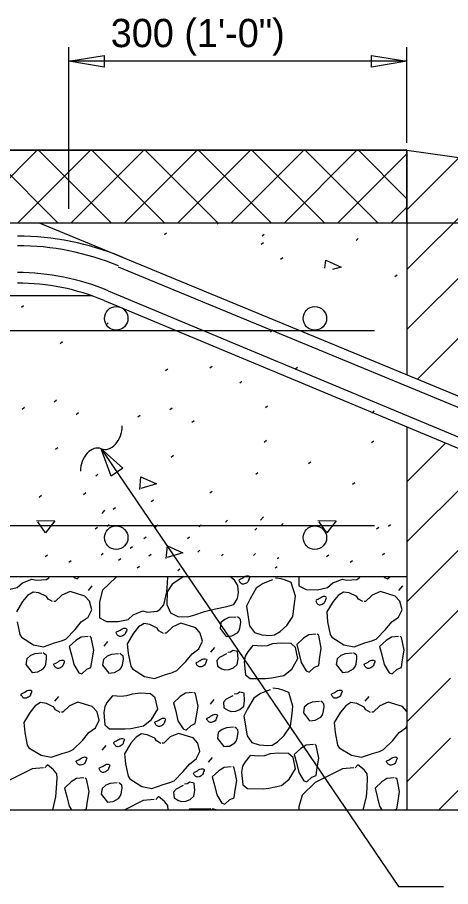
# Model space of a CAD drawing. Extents: x 3239 to 4230, y -4276 to -2494.
# Drawn here: x 3504.5 to 3550.5, y -4204.4 to -4112.2 of the extents above; entities that cross this region are included whole.
import ezdxf

# ---------------------------------------------------------------- set-up
doc = ezdxf.new("R2010")
doc.units = 0
doc.layers.add('2', color=7, linetype='Continuous')

msp = doc.modelspace()

# ---------------------------------------------------------------- linework, layer by layer
at = {"layer": '2'}
for p, q in [((3510.009, -4132.49), (3510.009, -4115.341)), ((3545.886, -4125.509), (3545.886, -4115.341)), ((3545.886, -4116.841), (3510.009, -4116.841)), ((3367.086, -4126.29), (3545.886, -4126.29)), ((3498.953, -4133.99), (3506.653, -4126.29)), ((3501.149, -4126.29), (3508.849, -4133.99)), ((3504.61, -4133.99), (3512.31, -4126.29)), ((3506.806, -4126.29), (3514.506, -4133.99)), ((3510.267, -4133.99), (3517.967, -4126.29)), ((3512.463, -4126.29), (3520.163, -4133.99)), ((3515.924, -4133.99), (3523.624, -4126.29)), ((3518.12, -4126.29), (3525.82, -4133.99)), ((3521.581, -4133.99), (3529.281, -4126.29)), ((3523.777, -4126.29), (3531.477, -4133.99)), ((3527.237, -4133.99), (3534.937, -4126.29)), ((3529.434, -4126.29), (3537.134, -4133.99)), ((3532.894, -4133.99), (3540.594, -4126.29)), ((3535.091, -4126.29), (3542.791, -4133.99)), ((3538.551, -4133.99), (3545.886, -4126.656)), ((3540.747, -4126.29), (3545.886, -4131.428)), ((3545.886, -4126.29), (3545.886, -4150.107)), ((3545.886, -4126.29), (3601.998, -4133.99)), ((3545.886, -4132.595), (3551.43, -4127.051)), ((3545.886, -4138.955), (3557.022, -4127.818)), ((3545.952, -4145.253), (3562.618, -4128.586)), ((3547, -4150.568), (3568.214, -4129.354)), ((3544.208, -4133.99), (3545.886, -4132.313)), ((3363.086, -4133.99), (3601.998, -4133.99)), ((3506.854, -4133.99), (3609.598, -4176.416)), ((3525.77, -4134.077), (3525.879, -4133.99)), ((3520.155, -4135.219), (3520.388, -4135.033)), ((3530.522, -4135.382), (3530.755, -4135.196)), ((3540.491, -4135.846), (3540.724, -4135.659)), ((3530.429, -4136.267), (3530.662, -4136.081)), ((3532.477, -4137.849), (3532.71, -4137.663)), ((3515.238, -4138.666), (3628.011, -4185.234)), ((3544.615, -4139.69), (3544.848, -4139.503)), ((3514.182, -4141.195), (3625.358, -4187.612)), ((3351.09, -4141.69), (3512.455, -4141.69)), ((3513.749, -4142.231), (3609.598, -4182.249)), ((3504.974, -4142.936), (3505.207, -4142.75)), ((3513.967, -4144.8), (3514.2, -4144.614)), ((3311.806, -4145.411), (3542.451, -4145.411)), ((3531.417, -4145.541), (3531.65, -4145.355)), ((3509.097, -4146.78), (3509.33, -4146.594)), ((3520.28, -4149.669), (3520.513, -4149.483)), ((3524.984, -4149.387), (3525.217, -4149.201)), ((3534.05, -4149.479), (3534.283, -4149.292)), ((3528.152, -4150.971), (3528.385, -4150.785)), ((3505.057, -4153.751), (3505.29, -4153.564)), ((3508.468, -4152.977), (3508.701, -4152.791)), ((3530.878, -4153.604), (3531.111, -4153.418)), ((3510.794, -4154.314), (3511.027, -4154.128)), ((3517.333, -4154.587), (3517.566, -4154.401)), ((3520.744, -4153.814), (3520.977, -4153.627)), ((3542.178, -4154.141), (3542.411, -4153.955)), ((3523.07, -4155.151), (3523.303, -4154.964)), ((3545.886, -4155.648), (3545.886, -4164.49)), ((3530.751, -4157.251), (3530.984, -4157.064)), ((3542.132, -4157.31), (3542.365, -4157.123)), ((3508.608, -4158.01), (3508.841, -4157.823)), ((3545.886, -4161.485), (3550.003, -4157.367)), ((3520.883, -4158.846), (3521.116, -4158.66)), ((3535.457, -4159.534), (3535.69, -4159.348)), ((3545.886, -4167.849), (3554.493, -4159.242)), ((3512.869, -4160.85), (3513.102, -4160.663)), ((3529.842, -4160.676), (3530.075, -4160.489)), ((3540.117, -4161.724), (3540.35, -4161.538)), ((3545.886, -4174.213), (3558.982, -4161.116)), ((3511.564, -4162.807), (3511.797, -4162.62)), ((3524.973, -4162.656), (3525.206, -4162.469)), ((3506.861, -4163.089), (3507.094, -4162.903)), ((3518.763, -4163.576), (3518.996, -4163.389)), ((3545.886, -4180.577), (3563.472, -4162.99)), ((3514.733, -4164.391), (3514.966, -4164.205)), ((3545.886, -4164.49), (3545.886, -4196.29)), ((3526.634, -4165.75), (3526.867, -4165.563)), ((3310.367, -4166.121), (3542.451, -4166.121)), ((3512.816, -4166.476), (3513.049, -4166.29)), ((3514.075, -4166.196), (3514.308, -4166.01)), ((3519.213, -4166.243), (3519.446, -4166.056)), ((3523.833, -4166.243), (3524.066, -4166.056)), ((3529.74, -4166.594), (3529.973, -4166.407)), ((3532.541, -4166.101), (3532.774, -4165.914)), ((3542.675, -4166.476), (3542.908, -4166.29)), ((3543.933, -4166.196), (3544.166, -4166.01)), ((3517.979, -4167.505), (3518.212, -4167.318)), ((3522.599, -4167.505), (3522.832, -4167.318)), ((3516.523, -4168.524), (3516.756, -4168.338)), ((3507.511, -4169.415), (3507.744, -4169.229)), ((3513.426, -4169.226), (3513.659, -4169.04)), ((3518.512, -4169.344), (3518.745, -4169.157)), ((3523.694, -4168.934), (3523.927, -4168.747)), ((3526.231, -4169.28), (3526.404, -4169.142)), ((3529.6, -4169.285), (3529.833, -4169.098)), ((3537.37, -4169.415), (3537.603, -4169.229)), ((3543.285, -4169.226), (3543.518, -4169.04)), ((3510.015, -4170), (3510.248, -4169.813)), ((3515.288, -4169.787), (3515.521, -4169.6)), ((3532.138, -4169.632), (3532.31, -4169.493)), ((3539.874, -4170), (3540.107, -4169.813)), ((3517.277, -4170.606), (3517.51, -4170.42)), ((3521.571, -4170.889), (3521.804, -4170.703)), ((3531.927, -4170.622), (3532.138, -4170.453)), ((3310.367, -4171.521), (3545.886, -4171.521)), ((3545.886, -4186.941), (3550.514, -4182.313)), ((3545.886, -4193.305), (3550.514, -4188.677)), ((3549.264, -4196.29), (3554.623, -4190.931)), ((3445.738, -4196.29), (3572.037, -4196.29))]:
    msp.add_line(p, q, dxfattribs=at)
for points in [[(3513.759, -4117.471), (3510.009, -4116.841), (3513.759, -4116.211)], [(3542.136, -4116.211), (3545.886, -4116.841), (3542.136, -4117.471)], [(3373.586, -4133.99), (3545.886, -4133.99), (3545.886, -4126.29), (3373.586, -4126.29)], [(3514.514, -4160.875), (3513.449, -4157.972), (3515.755, -4160.033)]]:
    msp.add_lwpolyline(points, close=True, dxfattribs=at)
for points in [[(3537.188, -4138.798), (3537.276, -4137.942), (3538.907, -4138.688), (3538.008, -4138.954)], [(3513.449, -4157.972), (3545.008, -4204.442), (3549.776, -4204.442)], [(3517.529, -4162.294), (3517.668, -4160.943), (3519.299, -4161.688), (3517.645, -4162.178)], [(3513.812, -4164.49), (3513.508, -4164.853)], [(3530.67, -4165.192), (3530.366, -4165.555)], [(3506.586, -4165.594), (3508.519, -4165.618), (3507.541, -4166.876), (3506.725, -4165.734)], [(3536.445, -4165.594), (3538.378, -4165.618), (3537.4, -4166.876), (3536.584, -4165.734)], [(3520.336, -4169.608), (3520.476, -4168.257), (3522.106, -4169.002), (3520.452, -4169.492)], [(3501.48, -4171.521), (3501.475, -4172.521), (3502.272, -4172.908), (3503.475, -4172.955), (3504.522, -4172.711), (3505.087, -4172.205), (3506.098, -4171.811), (3506.567, -4171.922), (3507.625, -4171.829), (3507.893, -4171.654), (3508.01, -4171.521)], [(3510.495, -4171.521), (3510.572, -4171.647), (3510.888, -4171.771), (3511.158, -4171.521)], [(3515.249, -4171.521), (3514.993, -4171.649), (3513.585, -4172.992), (3513.257, -4174.218), (3513.251, -4175.898), (3514.025, -4176.287), (3515.249, -4176.31), (3516.297, -4176.088), (3516.84, -4175.584), (3517.874, -4175.188), (3518.34, -4175.299), (3519.379, -4175.208), (3519.669, -4175.031), (3520.083, -4174.537), (3520.421, -4173.156), (3520.492, -4172.236), (3520.531, -4171.521)], [(3522.223, -4171.521), (3520.98, -4172.345), (3520.442, -4173.154), (3520.407, -4174.509), (3520.79, -4175.39), (3521.584, -4175.756), (3522.636, -4175.817), (3523.379, -4175.599), (3524.393, -4175.228), (3525.59, -4174.97), (3526.767, -4174.715), (3527.511, -4174.496), (3527.911, -4173.852), (3528.011, -4173.233), (3527.947, -4172.498), (3527.59, -4171.918), (3527.115, -4171.521)], [(3531.639, -4171.869), (3530.627, -4172.263), (3529.908, -4172.762), (3529.244, -4173.888), (3528.857, -4174.684), (3529.191, -4176.769), (3529.711, -4177.486), (3530.492, -4177.701), (3531.393, -4177.774), (3531.847, -4177.734), (3532.427, -4177.38), (3533.132, -4176.729), (3533.788, -4175.756), (3533.974, -4174.39), (3534.058, -4173.62), (3533.624, -4172.153), (3533.015, -4171.903), (3532.546, -4171.79), (3531.929, -4171.692)], [(3534.424, -4171.521), (3534.419, -4172.521), (3535.215, -4172.908), (3536.419, -4172.955), (3537.466, -4172.711), (3538.03, -4172.205), (3539.042, -4171.811), (3539.511, -4171.922), (3540.569, -4171.829), (3540.837, -4171.654), (3540.954, -4171.521)], [(3543.439, -4171.521), (3543.516, -4171.647), (3543.832, -4171.771), (3544.102, -4171.521)], [(3512.466, -4172.507), (3512.05, -4173.003)], [(3545.41, -4172.507), (3544.994, -4173.003)], [(3508.269, -4174.192), (3507.81, -4173.949), (3507.633, -4173.659), (3506.837, -4173.271), (3506.218, -4173.174), (3505.64, -4173.528), (3505.108, -4174.185), (3504.442, -4175.289)], [(3504.535, -4176.349), (3504.803, -4177.677), (3504.982, -4177.967), (3506.25, -4178.77), (3507.336, -4178.981), (3508.499, -4178.574), (3509.242, -4178.357), (3509.684, -4178.164), (3510.665, -4177.164), (3511.334, -4176.343), (3512.052, -4175.843), (3512.44, -4175.047), (3512.21, -4174.153), (3511.703, -4173.608), (3510.158, -4173.132), (3509.278, -4173.515), (3508.57, -4174.166), (3508.42, -4174.179)], [(3541.213, -4174.192), (3540.754, -4173.949), (3540.577, -4173.659), (3539.781, -4173.271), (3539.161, -4173.174), (3538.583, -4173.528), (3538.052, -4174.185), (3537.386, -4175.289), (3537.479, -4176.349), (3537.747, -4177.677), (3537.926, -4177.967), (3539.194, -4178.77), (3540.28, -4178.981), (3541.442, -4178.574), (3542.186, -4178.357), (3542.628, -4178.164), (3543.608, -4177.164), (3544.277, -4176.343), (3544.996, -4175.843), (3545.384, -4175.047), (3545.154, -4174.153), (3544.647, -4173.608), (3543.102, -4173.132), (3542.221, -4173.515), (3541.514, -4174.166), (3541.363, -4174.179)], [(3520.044, -4177.569), (3519.562, -4177.306), (3519.385, -4177.016), (3518.61, -4176.627), (3517.991, -4176.529), (3517.411, -4176.885), (3516.86, -4177.542), (3516.218, -4178.666), (3516.308, -4179.705), (3516.578, -4181.054), (3516.755, -4181.322), (3518.024, -4182.126), (3519.11, -4182.336), (3520.272, -4181.929), (3521.016, -4181.712), (3521.456, -4181.52), (3522.417, -4180.543), (3523.107, -4179.721), (3523.826, -4179.201), (3524.192, -4178.404), (3523.962, -4177.532), (3523.477, -4176.963), (3521.91, -4176.492), (3521.049, -4176.87), (3520.346, -4177.543), (3520.195, -4177.556)], [(3527.757, -4175.826), (3527, -4175.893), (3526.56, -4176.085), (3526.154, -4176.424), (3526.055, -4177.043), (3526.717, -4177.88), (3527.02, -4177.853), (3527.323, -4177.827), (3527.903, -4177.492), (3528.042, -4177.327), (3528.166, -4177.012), (3528.264, -4176.393), (3528.237, -4176.09), (3528.074, -4175.952), (3527.91, -4175.813)], [(3512.074, -4177.888), (3511.315, -4177.955), (3510.759, -4178.309), (3510.053, -4178.959), (3510.283, -4179.854), (3510.527, -4180.878), (3511.06, -4181.748), (3511.376, -4181.872), (3511.919, -4181.367), (3512.361, -4181.175), (3512.461, -4180.579), (3512.658, -4179.34), (3512.388, -4178.014), (3512.224, -4177.875)], [(3514.132, -4178.429), (3513.717, -4178.924)], [(3536.241, -4177.655), (3535.485, -4177.722), (3534.905, -4178.078), (3534.201, -4178.75), (3534.431, -4179.622), (3534.675, -4180.669), (3535.208, -4181.538), (3535.524, -4181.663), (3536.091, -4181.156), (3536.531, -4180.964), (3536.607, -4180.348), (3536.806, -4179.131), (3536.536, -4177.783), (3536.371, -4177.644)], [(3545.017, -4177.888), (3544.259, -4177.955), (3543.703, -4178.309), (3542.997, -4178.959), (3543.227, -4179.854), (3543.47, -4180.878), (3544.004, -4181.748), (3544.32, -4181.872), (3544.863, -4181.367), (3545.305, -4181.175), (3545.405, -4180.579), (3545.602, -4179.34), (3545.332, -4178.014), (3545.168, -4177.875)], [(3525.469, -4179.057), (3525.055, -4179.55)], [(3526.732, -4179.75), (3526.002, -4180.12), (3525.727, -4180.449), (3525.78, -4181.053), (3526.26, -4181.317), (3526.577, -4181.443), (3527.03, -4181.403), (3527.471, -4181.211), (3527.876, -4180.87), (3527.976, -4180.252), (3527.91, -4179.496), (3527.464, -4179.381), (3527.175, -4179.56), (3526.872, -4179.586)], [(3530.448, -4178.925), (3529.525, -4178.854), (3528.996, -4179.511), (3528.732, -4179.991), (3528.631, -4180.587), (3528.75, -4181.95), (3529.245, -4182.365), (3530.899, -4182.351), (3531.505, -4182.298), (3532.835, -4182.051), (3533.689, -4181.366), (3534.332, -4180.242), (3534.077, -4179.066), (3533.605, -4178.648), (3532.532, -4178.591), (3531.623, -4178.67), (3531.054, -4178.872), (3530.448, -4178.925)], [(3507.143, -4179.658), (3506.387, -4179.724), (3505.946, -4179.916), (3505.54, -4180.255), (3505.441, -4180.875), (3506.103, -4181.711), (3506.406, -4181.685), (3506.709, -4181.658), (3507.289, -4181.324), (3507.428, -4181.158), (3507.552, -4180.843), (3507.65, -4180.224), (3507.623, -4179.921), (3507.46, -4179.784), (3507.296, -4179.644)], [(3515.288, -4179.727), (3514.531, -4179.794), (3514.091, -4179.986), (3513.685, -4180.325), (3513.586, -4180.944), (3514.248, -4181.781), (3514.551, -4181.754), (3514.854, -4181.728), (3515.434, -4181.393), (3515.573, -4181.228), (3515.697, -4180.913), (3515.795, -4180.294), (3515.768, -4179.991), (3515.604, -4179.853), (3515.44, -4179.714)], [(3540.087, -4179.658), (3539.33, -4179.724), (3538.89, -4179.916), (3538.484, -4180.255), (3538.385, -4180.875), (3539.047, -4181.711), (3539.35, -4181.685), (3539.653, -4181.658), (3540.233, -4181.324), (3540.372, -4181.158), (3540.496, -4180.843), (3540.594, -4180.224), (3540.567, -4179.921), (3540.403, -4179.784), (3540.239, -4179.644)], [(3515.557, -4184.259), (3514.637, -4184.188), (3514.084, -4184.847), (3513.82, -4185.327), (3513.722, -4185.944), (3513.84, -4187.286), (3514.333, -4187.7), (3515.991, -4187.708), (3516.595, -4187.655), (3517.945, -4187.384), (3518.779, -4186.702), (3519.445, -4185.597), (3519.187, -4184.4), (3518.693, -4183.984), (3517.642, -4183.925), (3516.735, -4184.004), (3516.142, -4184.208), (3515.557, -4184.259)], [(3523.144, -4183.849), (3522.386, -4183.915), (3521.829, -4184.269), (3521.124, -4184.92), (3521.354, -4185.814), (3521.597, -4186.839), (3522.13, -4187.708), (3522.447, -4187.832), (3522.99, -4187.328), (3523.432, -4187.135), (3523.531, -4186.539), (3523.728, -4185.301), (3523.459, -4183.975), (3523.295, -4183.835)], [(3527.429, -4184.178), (3526.699, -4184.547), (3526.424, -4184.877), (3526.477, -4185.481), (3526.957, -4185.744), (3527.273, -4185.87), (3527.727, -4185.831), (3528.167, -4185.639), (3528.573, -4185.298), (3528.673, -4184.68), (3528.606, -4183.923), (3528.161, -4183.809), (3527.871, -4183.988), (3527.568, -4184.014)], [(3531.377, -4183.543), (3530.344, -4183.938), (3529.648, -4184.456), (3528.983, -4185.561), (3528.595, -4186.357), (3528.929, -4188.442), (3529.451, -4189.159), (3530.213, -4189.398), (3531.133, -4189.469), (3531.589, -4189.429), (3532.166, -4189.075), (3532.849, -4188.404), (3533.526, -4187.429), (3533.712, -4186.063), (3533.798, -4185.293), (3533.364, -4183.826), (3532.732, -4183.578), (3532.265, -4183.465), (3531.667, -4183.365)], [(3509.082, -4185.945), (3508.602, -4185.681), (3508.423, -4185.393), (3507.626, -4185.004), (3507.009, -4184.906), (3506.451, -4185.261), (3505.898, -4185.918), (3505.232, -4187.022), (3505.324, -4188.082), (3505.596, -4189.432), (3505.771, -4189.7), (3507.061, -4190.501), (3508.126, -4190.714), (3509.312, -4190.304), (3510.034, -4190.089), (3510.474, -4189.899), (3511.456, -4188.919), (3512.125, -4188.098), (3512.842, -4187.578), (3513.23, -4186.782), (3513.001, -4185.907), (3512.495, -4185.341), (3510.95, -4184.867), (3510.067, -4185.25), (3509.363, -4185.92), (3509.234, -4185.931)], [(3508.913, -4184.25), (3508.498, -4184.745)], [(3525.417, -4184.598), (3525.002, -4185.093)], [(3536.604, -4184.782), (3535.847, -4184.848), (3535.407, -4185.04), (3535.001, -4185.38), (3534.902, -4185.999), (3535.564, -4186.835), (3535.867, -4186.809), (3536.17, -4186.782), (3536.75, -4186.448), (3536.889, -4186.282), (3537.013, -4185.968), (3537.111, -4185.349), (3537.084, -4185.046), (3536.92, -4184.908), (3536.756, -4184.769)], [(3542.026, -4185.945), (3541.545, -4185.681), (3541.367, -4185.393), (3540.57, -4185.004), (3539.953, -4184.906), (3539.395, -4185.261), (3538.841, -4185.918), (3538.175, -4187.022), (3538.268, -4188.082), (3538.54, -4189.432), (3538.715, -4189.7), (3540.005, -4190.501), (3541.07, -4190.714), (3542.255, -4190.304), (3542.977, -4190.089), (3543.418, -4189.899), (3544.4, -4188.919), (3545.069, -4188.098), (3545.786, -4187.578), (3545.886, -4187.373)], [(3541.857, -4184.25), (3541.441, -4184.745)], [(3545.886, -4185.841), (3545.438, -4185.341), (3543.894, -4184.867), (3543.011, -4185.25), (3542.307, -4185.92), (3542.178, -4185.931)], [(3527.499, -4187.521), (3526.742, -4187.587), (3526.3, -4187.779), (3525.871, -4188.099), (3525.773, -4188.718), (3526.457, -4189.574), (3526.76, -4189.548), (3527.063, -4189.521), (3527.643, -4189.165), (3527.759, -4189.002), (3527.884, -4188.685), (3527.982, -4188.068), (3527.958, -4187.786), (3527.794, -4187.649), (3527.628, -4187.51)], [(3519.782, -4189.242), (3519.302, -4188.979), (3519.123, -4188.689), (3518.329, -4188.323), (3517.711, -4188.225), (3517.153, -4188.58), (3516.598, -4189.215), (3515.934, -4190.341), (3516.027, -4191.401), (3516.297, -4192.729), (3516.474, -4193.019), (3517.762, -4193.799), (3518.826, -4194.011), (3520.012, -4193.602), (3520.736, -4193.409), (3521.176, -4193.216), (3522.157, -4192.216), (3522.847, -4191.393), (3523.542, -4190.874), (3523.932, -4190.099), (3523.702, -4189.205), (3523.195, -4188.638), (3521.65, -4188.186), (3520.768, -4188.545), (3520.085, -4189.216), (3519.933, -4189.229)], [(3513.923, -4189.474), (3513.508, -4189.969)], [(3535.962, -4189.352), (3535.203, -4189.418), (3534.647, -4189.772), (3533.941, -4190.423), (3534.171, -4191.317), (3534.415, -4192.342), (3534.948, -4193.211), (3535.264, -4193.335), (3535.807, -4192.831), (3536.249, -4192.639), (3536.349, -4192.043), (3536.546, -4190.804), (3536.276, -4189.478), (3536.112, -4189.339)], [(3530.186, -4190.598), (3529.265, -4190.527), (3528.712, -4191.186), (3528.449, -4191.666), (3528.351, -4192.283), (3528.468, -4193.625), (3528.962, -4194.039), (3530.619, -4194.047), (3531.224, -4193.994), (3532.573, -4193.723), (3533.408, -4193.041), (3534.074, -4191.936), (3533.815, -4190.739), (3533.322, -4190.323), (3532.271, -4190.264), (3531.363, -4190.343), (3530.77, -4190.547), (3530.186, -4190.598)], [(3525.208, -4190.728), (3524.793, -4191.223)], [(3507.309, -4191.831), (3506.12, -4191.935), (3503.219, -4193.409), (3501.833, -4194.751), (3501.484, -4195.98), (3501.482, -4196.29)], [(3508.311, -4196.29), (3508.645, -4194.896), (3508.718, -4193.995), (3508.778, -4192.922), (3508.738, -4192.469), (3508.396, -4192.041), (3507.738, -4191.51), (3507.46, -4191.818)], [(3527.254, -4191.72), (3526.496, -4191.787), (3525.939, -4192.141), (3525.234, -4192.791), (3525.464, -4193.685), (3525.707, -4194.71), (3526.24, -4195.58), (3526.557, -4195.704), (3527.1, -4195.199), (3527.542, -4195.007), (3527.641, -4194.411), (3527.838, -4193.172), (3527.569, -4191.846), (3527.405, -4191.707)], [(3540.253, -4191.831), (3539.064, -4191.935), (3536.163, -4193.409), (3534.777, -4194.751), (3534.428, -4195.98), (3534.426, -4196.29)], [(3541.255, -4196.29), (3541.589, -4194.896), (3541.662, -4193.995), (3541.722, -4192.922), (3541.682, -4192.469), (3541.339, -4192.041), (3540.682, -4191.51), (3540.404, -4191.818)], [(3511.586, -4192.904), (3510.828, -4192.971), (3510.271, -4193.325), (3509.566, -4193.976), (3509.796, -4194.87), (3510.039, -4195.895), (3510.282, -4196.29)], [(3511.646, -4196.29), (3511.874, -4196.191), (3511.973, -4195.595), (3512.17, -4194.357), (3511.901, -4193.03), (3511.737, -4192.891)], [(3544.53, -4192.904), (3543.771, -4192.971), (3543.215, -4193.325), (3542.51, -4193.976), (3542.74, -4194.87), (3542.983, -4195.895), (3543.225, -4196.29)], [(3544.59, -4196.29), (3544.817, -4196.191), (3544.917, -4195.595), (3545.114, -4194.357), (3544.844, -4193.03), (3544.68, -4192.891)], [(3515.149, -4193.42), (3514.392, -4193.486), (3513.952, -4193.678), (3513.546, -4194.017), (3513.446, -4194.637), (3514.109, -4195.473), (3514.412, -4195.447), (3514.715, -4195.42), (3515.294, -4195.086), (3515.433, -4194.92), (3515.558, -4194.606), (3515.655, -4193.986), (3515.629, -4193.683), (3515.465, -4193.546), (3515.301, -4193.407)], [(3522.135, -4193.722), (3521.405, -4194.091), (3521.13, -4194.42), (3521.183, -4195.025), (3521.663, -4195.288), (3521.979, -4195.414), (3522.433, -4195.374), (3522.873, -4195.182), (3523.279, -4194.841), (3523.378, -4194.224), (3523.312, -4193.467), (3522.867, -4193.352), (3522.577, -4193.531), (3522.274, -4193.558)], [(3520.549, -4196.29), (3520.55, -4196.28), (3520.512, -4195.846), (3520.171, -4195.418), (3519.512, -4194.865), (3519.235, -4195.195)], [(3519.085, -4195.208), (3517.894, -4195.312), (3515.942, -4196.29)], [(3525.097, -4196.185), (3522.835, -4196.232), (3522.747, -4196.29)], [(3525.66, -4196.29), (3525.247, -4196.172), (3525.165, -4196.29)]]:
    msp.add_lwpolyline(points, dxfattribs=at)
for centre in [(3515.041, -4144.128), (3536.127, -4144.128), (3515.041, -4167.404), (3536.127, -4167.404)]:
    msp.add_circle(centre, 1.247, dxfattribs=at)
for radius in [28.863, 27.85, 25, 23.878]:
    msp.add_arc((3504.55, -4164.265), radius, 67.33892, 90, dxfattribs=at)
for centre, major_axis, end_param in [((3514.072, -4155.866), (0.464, 2.154), 5.017712), ((3512.826, -4160.079), (-0.464, -2.154), 4.989369)]:
    msp.add_ellipse(centre, major_axis=major_axis, ratio=0.707981, start_param=3.034942, end_param=end_param, dxfattribs=at)
for points in [[(3529.11, -4171.852), (3529.041, -4172.053), (3528.88, -4172.221), (3528.453, -4172.323), (3528.198, -4172.149), (3528.089, -4171.896), (3528.359, -4171.743), (3528.878, -4171.457), (3529.189, -4171.518), (3529.09, -4171.876)], [(3537.235, -4174.061), (3537.164, -4174.263), (3537.003, -4174.407), (3536.579, -4174.532), (3536.323, -4174.358), (3536.236, -4174.104), (3536.504, -4173.928), (3537.004, -4173.666), (3537.336, -4173.725), (3537.235, -4174.061)], [(3516.065, -4177.417), (3515.994, -4177.618), (3515.833, -4177.764), (3515.409, -4177.888), (3515.153, -4177.713), (3515.044, -4177.463), (3515.314, -4177.307), (3515.833, -4177.023), (3516.144, -4177.083), (3516.067, -4177.438)], [(3524.539, -4180.641), (3524.47, -4180.843), (3524.31, -4181.01), (3523.883, -4181.113), (3523.631, -4180.959), (3523.542, -4180.707), (3523.81, -4180.53), (3524.312, -4180.269), (3524.619, -4180.307), (3524.541, -4180.663)], [(3509.449, -4180.803), (3509.378, -4181.004), (3509.217, -4181.15), (3508.793, -4181.274), (3508.537, -4181.099), (3508.429, -4180.849), (3508.699, -4180.693), (3509.217, -4180.407), (3509.528, -4180.469), (3509.429, -4180.826)], [(3542.393, -4180.803), (3542.322, -4181.004), (3542.161, -4181.15), (3541.736, -4181.274), (3541.481, -4181.099), (3541.372, -4180.849), (3541.642, -4180.693), (3542.161, -4180.407), (3542.472, -4180.469), (3542.373, -4180.826)], [(3505.966, -4183.977), (3505.895, -4184.178), (3505.734, -4184.324), (3505.31, -4184.448), (3505.054, -4184.273), (3504.946, -4184.023), (3505.216, -4183.867), (3505.734, -4183.581), (3506.045, -4183.643), (3505.946, -4184)], [(3538.91, -4183.977), (3538.839, -4184.178), (3538.678, -4184.324), (3538.253, -4184.448), (3537.998, -4184.273), (3537.889, -4184.023), (3538.159, -4183.867), (3538.678, -4183.581), (3538.989, -4183.643), (3538.89, -4184)], [(3520.171, -4186.972), (3520.1, -4187.173), (3519.94, -4187.319), (3519.515, -4187.443), (3519.259, -4187.269), (3519.151, -4187.018), (3519.421, -4186.862), (3519.94, -4186.577), (3520.25, -4186.638), (3520.152, -4186.995)], [(3525.674, -4186.554), (3525.603, -4186.755), (3525.443, -4186.901), (3525.018, -4187.025), (3524.762, -4186.851), (3524.654, -4186.6), (3524.924, -4186.444), (3525.443, -4186.159), (3525.754, -4186.22), (3525.655, -4186.578)], [(3515.803, -4189.09), (3515.736, -4189.313), (3515.573, -4189.459), (3515.127, -4189.584), (3514.895, -4189.408), (3514.784, -4189.157), (3515.053, -4188.98), (3515.575, -4188.718), (3515.882, -4188.756), (3515.783, -4189.113)], [(3511.817, -4191.082), (3511.747, -4191.283), (3511.586, -4191.429), (3511.161, -4191.553), (3510.906, -4191.379), (3510.797, -4191.128), (3511.067, -4190.972), (3511.586, -4190.687), (3511.897, -4190.748), (3511.798, -4191.105)], [(3544.761, -4191.082), (3544.69, -4191.283), (3544.53, -4191.429), (3544.105, -4191.553), (3543.849, -4191.379), (3543.741, -4191.128), (3544.011, -4190.972), (3544.53, -4190.687), (3544.84, -4190.748), (3544.742, -4191.105)], [(3514.25, -4191.848), (3514.179, -4192.05), (3514.018, -4192.196), (3513.594, -4192.319), (3513.338, -4192.145), (3513.23, -4191.894), (3513.5, -4191.739), (3514.019, -4191.453), (3514.329, -4191.514), (3514.23, -4191.872)], [(3524.281, -4192.336), (3524.21, -4192.537), (3524.049, -4192.683), (3523.625, -4192.807), (3523.369, -4192.632), (3523.261, -4192.382), (3523.531, -4192.226), (3524.05, -4191.941), (3524.36, -4192.002), (3524.261, -4192.359)]]:
    msp.add_spline(points, degree=3, dxfattribs=at)

# ---------------------------------------------------------------- texts
msp.add_text('300 (1\'-0")', height=3, dxfattribs=at).set_placement((3514.461, -4115.341))

doc.saveas('drawing.dxf')
